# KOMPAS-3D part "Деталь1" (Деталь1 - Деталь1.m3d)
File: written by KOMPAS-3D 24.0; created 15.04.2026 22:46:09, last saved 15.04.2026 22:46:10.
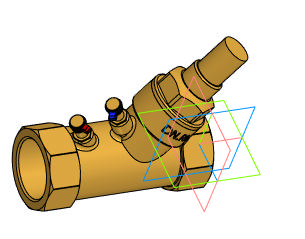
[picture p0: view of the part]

Document properties: Автор: tyuri; Полное имя файла: D:\Аутсорс\VB0000P-T Клапан балансировочный статический DN.ru\DN32\Исходные данные\Деталь1 - Деталь1.m3d

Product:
- Body: Твердое тело1  | qty 1
- Part/product: Деталь1
    additional columns: Типовые

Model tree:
1. Твердое тело1  (labels: Твердое тело1)
2. Изменить положение граней:1  (labels: Грань.Твердое тело1)
     Расстояние = 2.5
3. Изменить положение граней:2  (labels: Грань.Твердое тело1)
     Расстояние = 2.5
